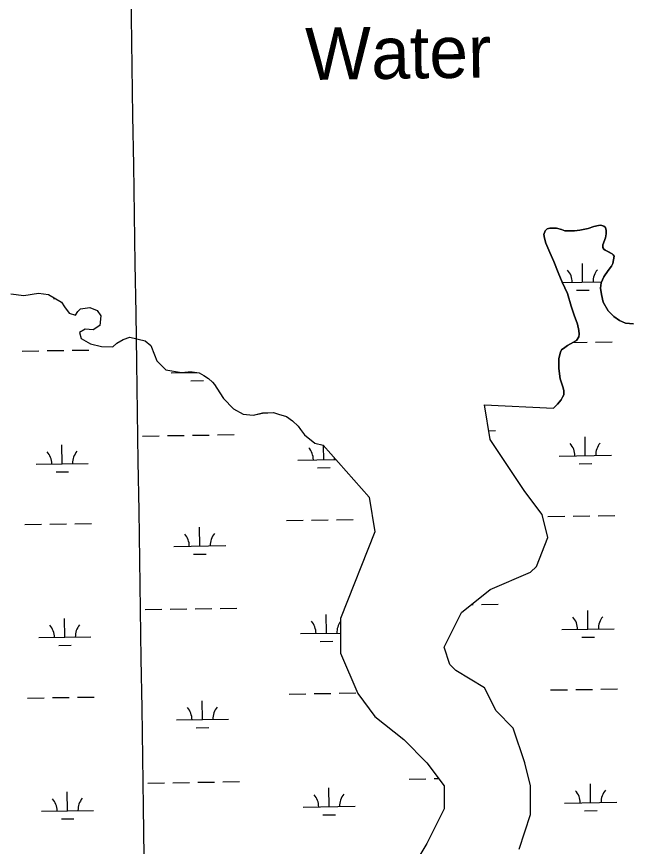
# Model space of a CAD drawing. Extents: x 3823584 to 3861785, y 301729 to 327625.
# Drawn here: x 3838149 to 3839325, y 310651 to 312242 of the extents above; entities that cross this region are included whole.
import ezdxf

# ---------------------------------------------------------------- set-up
doc = ezdxf.new("R2010")
doc.units = 0
for name, color, linetype in [('V-GRID-MAJR', 7, 'Continuous'), ('V-RIVR-IDEN', 7, 'Continuous'), ('V-TOPO-SHOR', 7, 'Continuous'), ('V-WETL-SWMP', 7, 'Continuous')]:
    doc.layers.add(name, color=color, linetype=linetype)

msp = doc.modelspace()

# ---------------------------------------------------------------- linework, layer by layer
at = {"layer": 'V-GRID-MAJR'}
msp.add_spline([(3838444.8910000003, 307319.343), (3838352.38, 313376.366), (3838259.823, 319436.473), (3838167.2660000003, 325496.576), (3838167.219, 325499.664)], degree=3, dxfattribs=at)
at = {"layer": 'V-TOPO-SHOR'}
for p, q in [((3838163.383548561, 311707.18858107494), (3838191.298548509, 311711.1795807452)), ((3838191.298548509, 311711.1795807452), (3838210.2405485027, 311709.18358070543)), ((3838138.4595485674, 311710.18158111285), (3838163.383548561, 311707.18858107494)), ((3838210.2405485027, 311709.18358070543), (3838235.1645485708, 311694.22058113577)), ((3838235.1645485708, 311694.22058113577), (3838241.1455486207, 311685.24258145)), ((3838241.1455486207, 311685.24258145), (3838250.1185486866, 311673.27258186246)), ((3838267.066548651, 311676.26458164), (3838272.051548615, 311681.2525814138)), ((3838272.051548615, 311681.2525814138), (3838289.9965485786, 311684.2455811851)), ((3838289.9965485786, 311684.2455811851), (3838303.954548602, 311678.26058133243)), ((3838250.1185486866, 311673.27258186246), (3838262.0825486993, 311669.28258194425)), ((3838262.0825486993, 311669.28258194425), (3838267.066548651, 311676.26458164)), ((3838303.954548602, 311678.26058133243), (3838310.9335486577, 311668.2845816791)), ((3838310.9335486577, 311668.2845816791), (3838308.939548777, 311649.33158243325)), ((3838308.939548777, 311649.33158243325), (3838295.9785488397, 311641.3505828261)), ((3838281.024548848, 311642.34858288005), (3838270.0575488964, 311636.36358318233)), ((3838270.0575488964, 311636.36358318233), (3838273.048548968, 311624.392583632)), ((3838295.9785488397, 311641.3505828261), (3838281.024548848, 311642.34858288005)), ((3838273.048548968, 311624.392583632), (3838290.993549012, 311614.4175839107)), ((3838333.863549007, 311608.4325838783), (3838341.838548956, 311615.4145835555)), ((3838341.838548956, 311615.4145835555), (3838353.8025489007, 311622.3975832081)), ((3838353.8025489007, 311622.3975832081), (3838366.762548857, 311627.385582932)), ((3838366.762548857, 311627.385582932), (3838395.674548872, 311620.4025830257)), ((3838395.674548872, 311620.4025830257), (3838406.641548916, 311611.42458330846)), ((3838290.993549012, 311614.4175839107), (3838311.9305490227, 311609.4295839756)), ((3838311.9305490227, 311609.4295839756), (3838333.863549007, 311608.4325838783)), ((3838406.641548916, 311611.42458330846), (3838413.6195490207, 311593.4685839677)), ((3838413.6195490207, 311593.4685839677), (3838418.6045490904, 311581.4985844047)), ((3838418.6045490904, 311581.4985844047), (3838435.552549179, 311564.5405849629)), ((3838435.552549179, 311564.5405849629), (3838465.460549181, 311559.5525849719)), ((3838465.460549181, 311559.5525849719), (3838478.421549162, 311560.55058485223)), ((3838478.421549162, 311560.55058485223), (3838486.3965491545, 311560.55058480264)), ((3838486.3965491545, 311560.55058480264), (3838499.3575491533, 311558.55458480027)), ((3838499.3575491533, 311558.55458480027), (3838508.3295491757, 311553.5675849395)), ((3838508.3295491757, 311553.5675849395), (3838517.302549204, 311547.5815851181)), ((3838517.302549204, 311547.5815851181), (3838525.2785492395, 311540.59958534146)), ((3838525.2785492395, 311540.59958534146), (3838529.266549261, 311536.6085854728)), ((3838529.266549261, 311536.6085854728), (3838539.23554935, 311520.648586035)), ((3838539.23554935, 311520.648586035), (3838546.2145494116, 311509.67558642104)), ((3838546.2145494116, 311509.67558642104), (3838565.1565495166, 311489.7245870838)), ((3838565.1565495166, 311489.7245870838), (3838584.09854956, 311479.7485873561)), ((3839058.1133026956, 311431.0057058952), (3839047.055311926, 311497.4016969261)), ((3839047.055311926, 311497.4016969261), (3839179.575, 311491.261)), ((3838584.09854956, 311479.7485873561), (3838603.041549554, 311477.75358731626)), ((3838603.041549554, 311477.75358731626), (3838620.986549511, 311481.74458704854)), ((3838620.986549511, 311481.74458704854), (3838641.9225494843, 311482.7415868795)), ((3838641.9225494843, 311482.7415868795), (3838651.8915494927, 311479.7485869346)), ((3838651.8915494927, 311479.7485869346), (3838666.846549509, 311474.76158703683)), ((3838666.846549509, 311474.76158703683), (3838678.8095495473, 311466.78058727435)), ((3838678.8095495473, 311466.78058727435), (3838689.776549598, 311456.80558759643)), ((3838689.776549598, 311456.80558759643), (3838693.7645496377, 311449.82258784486)), ((3838693.7645496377, 311449.82258784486), (3838701.7395496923, 311439.84758818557)), ((3838701.7395496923, 311439.84758818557), (3838721.6795497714, 311423.88658868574)), ((3839124.4622827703, 311331.412725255), (3839058.1133026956, 311431.0057058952)), ((3838721.6795497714, 311423.88658868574), (3838737.424791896, 311419.9449808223)), ((3838737.424791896, 311419.9449808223), (3838825.890792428, 311320.3519841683)), ((3839157.6372734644, 311287.14973429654), (3839124.4622827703, 311331.412725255)), ((3838825.890792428, 311320.3519841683), (3838836.9487928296, 311253.956986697)), ((3839168.69526686, 311242.8857407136), (3839157.6372734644, 311287.14973429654)), ((3838836.9487928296, 311253.956986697), (3838770.5997939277, 311087.9679936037)), ((3839146.579262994, 311187.55574446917), (3839168.69526686, 311242.8857407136)), ((3839135.520263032, 311176.4897444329), (3839146.579262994, 311187.55574446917)), ((3839058.113268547, 311143.292739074), (3839135.520263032, 311176.4897444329)), ((3839002.822270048, 311099.0287376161), (3839058.113268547, 311143.292739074)), ((3838969.6472662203, 311032.6337413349), (3839002.822270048, 311099.0287376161)), ((3838770.5997939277, 311087.9679936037), (3838770.5997943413, 311021.5729962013)), ((3838980.705260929, 310999.43574647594), (3838969.6472662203, 311032.6337413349)), ((3838770.5997943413, 311021.5729962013), (3838803.77479479, 310944.1109990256)), ((3838991.764258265, 310988.36974906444), (3838980.705260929, 310999.43574647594)), ((3839047.0552475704, 310955.17175945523), (3838991.764258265, 310988.36974906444)), ((3839069.1712396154, 310910.9087671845), (3839047.0552475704, 310955.17175945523)), ((3838803.77479479, 310944.1109990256), (3838836.9487950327, 310899.84800055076)), ((3838836.9487950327, 310899.84800055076), (3838892.240795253, 310855.5840019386)), ((3839102.346231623, 310877.7107749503), (3839069.1712396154, 310910.9087671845)), ((3839124.462221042, 310811.3157852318), (3839102.346231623, 310877.7107749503)), ((3838892.240795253, 310855.5840019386), (3838936.4727954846, 310811.3210033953)), ((3838936.4727954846, 310811.3210033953), (3838969.647795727, 310767.0570049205)), ((3839135.520214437, 310767.0517916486), (3839124.462221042, 310811.3157852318)), ((3838969.647795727, 310767.0570049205), (3838969.6477960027, 310722.7930066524)), ((3839135.5202078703, 310711.7227980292), (3839135.520214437, 310767.0517916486)), ((3838969.6477960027, 310722.7930066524), (3838936.4727964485, 310656.3980094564)), ((3839113.4042026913, 310645.326803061), (3839135.5202078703, 310711.7227980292)), ((3838936.4727964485, 310656.3980094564), (3838903.2987968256, 310601.0680118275))]:
    msp.add_line(p, q, dxfattribs=at)
msp.add_lwpolyline([(3839332.98, 311652.49), (3839317.823, 311654.02), (3839306.199, 311658.904), (3839294.957, 311666.941), (3839284.498, 311677.338), (3839274.805, 311694.431), (3839271.415, 311708.78500000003), (3839269.41, 311721.178), (3839270.7600000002, 311731.217), (3839276.038, 311742.844), (3839284.267, 311754.87200000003), (3839290.736, 311763.156), (3839293.474, 311768.476), (3839295.598, 311782.257), (3839294.214, 311784.811), (3839291.846, 311786.97000000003), (3839283.568, 311791.076), (3839278.643, 311793.62200000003), (3839276.273, 311795.778), (3839274.2970000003, 311798.723), (3839274.2800000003, 311804.431), (3839276.2320000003, 311809.553), (3839279.161, 311817.63), (3839280.318, 311825.308), (3839280.3000000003, 311831.803), (3839279.298, 311837.504), (3839275.946, 311840.251), (3839270.43, 311841.80700000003), (3839265.904, 311841.402), (3839256.664, 311839.208), (3839245.85, 311835.634), (3839229.921, 311832.243), (3839219.494, 311831.031), (3839210.444, 311830.80700000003), (3839201.194, 311831.174), (3839194.693, 311833.318), (3839185.043, 311836.044), (3839179.9250000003, 311836.226), (3839172.644, 311836.204), (3839167.336, 311834.811), (3839163.213, 311831.25800000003), (3839161.071, 311824.166), (3839162.273, 311816.693), (3839164.86, 311807.05700000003), (3839172.585, 311789.76300000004), (3839180.1180000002, 311772.075), (3839188.2460000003, 311751.044), (3839196.174, 311732.569), (3839206.078, 311710.756), (3839213.629, 311686.376), (3839219.1890000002, 311669.273), (3839225.341, 311651.777), (3839228.33, 311639.782), (3839228.94, 311632.7), (3839228.168, 311627.58), (3839223.269, 311620.875), (3839222.286, 311620.283), (3839206.572, 311610.987), (3839200.876, 311607.231), (3839194.593, 311602.68700000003), (3839192.637, 311598.351), (3839189.524, 311586.143), (3839189.778, 311567.25), (3839192.002, 311546.989), (3839197.556, 311532.049), (3839199.35, 311524.578), (3839199.559, 311520.249), (3839198.98, 311516.706), (3839196.829, 311511.977), (3839193.892, 311506.851), (3839187.423, 311498.76300000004), (3839179.575, 311491.261)], dxfattribs=at)
at = {"layer": 'V-WETL-SWMP'}
for p, q in [((3839235.371810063, 311732.5728008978), (3839234.8168063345, 311768.56852031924)), ((3839196.4448028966, 311731.9725961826), (3839271.628512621, 311733.1318329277)), ((3839223.6111331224, 311716.9586330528), (3839247.6082793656, 311717.3286383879)), ((3838219.9154846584, 311701.48230258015), (3838222.9896803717, 311701.5297027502)), ((3839216.4455281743, 311616.8352682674), (3839243.742614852, 311617.2561544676)), ((3839259.7407123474, 311617.50282469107), (3839291.7369073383, 311617.99616513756)), ((3838160.056487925, 311600.5464690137), (3838192.052684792, 311601.0398094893)), ((3838208.0507832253, 311601.28647972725), (3838240.0469800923, 311601.7798202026)), ((3838256.045078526, 311602.0264904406), (3838288.0412753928, 311602.51983091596)), ((3838445.582441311, 311558.5133965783), (3838494.7066282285, 311559.2708287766)), ((3838483.8158232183, 311543.6700726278), (3838507.812970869, 311544.04007798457)), ((3838534.579205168, 311439.8003434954), (3838566.575402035, 311440.29368397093)), ((3839055.311282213, 311447.83000342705), (3839068.422676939, 311448.03216438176)), ((3838390.596319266, 311437.58031135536), (3838422.592516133, 311438.0736518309)), ((3838438.5906145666, 311438.32032206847), (3838470.586811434, 311438.81366254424)), ((3838486.5849098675, 311439.06033278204), (3838518.5811067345, 311439.5536732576)), ((3839240.5005841, 311399.93735760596), (3839239.9455803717, 311435.9330770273)), ((3838236.8049763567, 311384.46101506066), (3838236.2499680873, 311420.4567358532)), ((3838738.653325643, 311392.19887541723), (3838738.2396604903, 311419.02762042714)), ((3838688.6592680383, 311391.4280309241), (3838761.754576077, 311392.5550671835)), ((3839190.506529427, 311399.16651315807), (3839290.4946387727, 311400.7082020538)), ((3838186.8109187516, 311383.69017056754), (3838286.7990339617, 311385.23185955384)), ((3838726.8926499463, 311376.5847069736), (3838750.8897975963, 311376.9547123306)), ((3839228.73990716, 311384.3231897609), (3839252.7370534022, 311384.69319509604)), ((3838225.0443006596, 311368.846846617), (3838249.04144831, 311369.216851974)), ((3839168.880901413, 311283.3873600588), (3839200.877096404, 311283.8807005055)), ((3839216.8751938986, 311284.127370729), (3839248.8713888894, 311284.62071117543)), ((3839264.8694863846, 311284.8673813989), (3839296.8656813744, 311285.3607218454)), ((3838165.1853039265, 311267.9110130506), (3838197.1815007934, 311268.40435352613)), ((3838213.179599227, 311268.65102376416), (3838245.175796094, 311269.1443642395)), ((3838261.1738945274, 311269.3910344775), (3838293.1700913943, 311269.8843749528)), ((3838667.0336532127, 311275.64887340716), (3838699.0298500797, 311276.1422138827)), ((3838715.027948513, 311276.38888412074), (3838747.02414538, 311276.88222459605)), ((3838763.0222438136, 311277.128894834), (3838795.0184406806, 311277.6222353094)), ((3838500.7053149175, 311226.6487851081), (3838500.150306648, 311262.6445059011)), ((3838450.711257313, 311225.8779406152), (3838550.6993725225, 311227.419629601)), ((3838488.9446392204, 311211.03461666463), (3838512.94178687, 311211.4046220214)), ((3838443.7194305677, 311105.6848661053), (3838475.715627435, 311106.1782065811)), ((3838491.7137258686, 311106.4248768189), (3838523.7099227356, 311106.91821729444)), ((3838539.7080211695, 311107.16488753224), (3838571.704218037, 311107.6582280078)), ((3839022.280354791, 311114.60618629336), (3839025.55715849, 311114.6567104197)), ((3839041.5552559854, 311114.9033806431), (3839073.5514509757, 311115.3967210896)), ((3838395.7251352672, 311104.9448553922), (3838427.721332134, 311105.43819586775)), ((3838743.7821416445, 311059.5634194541), (3838743.227133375, 311095.55914024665)), ((3839245.6293581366, 311067.3019143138), (3839245.0743544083, 311103.2976337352)), ((3838241.9337923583, 311051.8255590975), (3838241.3787840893, 311087.8212798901)), ((3838693.78808404, 311058.792574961), (3838770.599794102, 311059.9769133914)), ((3839195.635303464, 311066.531069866), (3839295.6234128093, 311068.07275876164)), ((3838191.9397347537, 311051.0547146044), (3838291.9278499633, 311052.5964035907)), ((3838732.021465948, 311043.94925101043), (3838756.018613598, 311044.31925636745)), ((3839233.868681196, 311051.6877464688), (3839257.8658274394, 311052.0577518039)), ((3838230.173116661, 311036.21139065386), (3838254.1702643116, 311036.5813960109)), ((3839174.00967545, 310950.75191676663), (3839206.0058704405, 310951.24525721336)), ((3839222.0039679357, 310951.49192743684), (3839254.0001629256, 310951.9852678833)), ((3839269.998260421, 310952.23193810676), (3839301.994455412, 310952.72527855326)), ((3838170.3141199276, 310935.27555708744), (3838202.310316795, 310935.768897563)), ((3838218.308415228, 310936.015567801), (3838250.3046120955, 310936.50890827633)), ((3838266.302710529, 310936.75557851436), (3838298.298907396, 310937.2489189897)), ((3838672.162469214, 310943.013417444), (3838704.1586660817, 310943.50675791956)), ((3838720.1567645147, 310943.7534281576), (3838752.152961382, 310944.2467686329)), ((3838768.1510598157, 310944.49343887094), (3838800.1472566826, 310944.98677934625)), ((3838505.8341309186, 310894.013329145), (3838505.279122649, 310930.00904993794)), ((3838455.8400733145, 310893.24248465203), (3838555.828188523, 310894.78417363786)), ((3838494.073455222, 310878.39916070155), (3838518.070602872, 310878.76916605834)), ((3838400.8539512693, 310772.30939942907), (3838432.8501481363, 310772.80273990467)), ((3838448.8482465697, 310773.0494101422), (3838480.8444434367, 310773.542750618)), ((3838496.84254187, 310773.78942085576), (3838528.838738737, 310774.2827613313)), ((3838544.8368371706, 310774.5294315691), (3838576.8330340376, 310775.02277204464)), ((3838902.7023005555, 310780.0472597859), (3838934.6984974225, 310780.5406002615)), ((3838950.696595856, 310780.787270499), (3838959.258291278, 310780.9192809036)), ((3838748.9109576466, 310726.92796349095), (3838748.3559493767, 310762.9236842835)), ((3839250.7581321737, 310734.66647102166), (3839250.2031284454, 310770.662190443)), ((3838247.06260836, 310719.1901031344), (3838246.50760009, 310755.18582392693)), ((3838698.9169000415, 310726.1571189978), (3838798.905015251, 310727.6988079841)), ((3839200.764077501, 310733.8956265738), (3839300.7521868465, 310735.4373154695)), ((3838197.0685507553, 310718.41925864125), (3838297.0566659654, 310719.96094762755)), ((3838737.150281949, 310711.3137950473), (3838761.147429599, 310711.6838004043)), ((3839238.9974552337, 310719.05230317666), (3839262.994601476, 310719.42230851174)), ((3838235.301932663, 310703.5759346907), (3838259.2990803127, 310703.94594004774))]:
    msp.add_line(p, q, dxfattribs=at)
for points in [[(3839113.404, 310645.327), (3839135.52, 310711.723), (3839135.52, 310767.052), (3839124.4620000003, 310811.316), (3839102.346, 310877.711), (3839069.171, 310910.909), (3839047.055, 310955.172), (3838991.764, 310988.37), (3838980.705, 310999.436), (3838969.647, 311032.634), (3839002.822, 311099.029), (3839058.113, 311143.293), (3839135.52, 311176.49), (3839146.579, 311187.556), (3839168.6950000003, 311242.886), (3839157.637, 311287.15), (3839124.4620000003, 311331.413), (3839058.113, 311431.006), (3839047.055, 311497.402), (3839179.574, 311491.262), (3839187.423, 311498.76300000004), (3839193.893, 311506.851), (3839196.83, 311511.976), (3839198.98, 311516.705), (3839199.56, 311520.249), (3839199.35, 311524.578), (3839197.557, 311532.05), (3839192.003, 311546.989), (3839189.778, 311567.251), (3839189.525, 311586.142), (3839192.637, 311598.352), (3839194.592, 311602.68700000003), (3839200.876, 311607.232), (3839206.571, 311610.987), (3839223.268, 311620.876), (3839228.168, 311627.581), (3839228.94, 311632.7), (3839228.329, 311639.783), (3839225.341, 311651.777), (3839219.1890000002, 311669.273), (3839213.628, 311686.377), (3839206.078, 311710.755), (3839196.174, 311732.569), (3839188.247, 311751.043), (3839180.117, 311772.075), (3839172.586, 311789.76300000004), (3839164.86, 311807.05700000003), (3839162.273, 311816.692), (3839161.071, 311824.166), (3839163.214, 311831.257), (3839167.336, 311834.811), (3839172.645, 311836.204), (3839179.926, 311836.226), (3839185.043, 311836.044), (3839194.693, 311833.318), (3839201.194, 311831.173), (3839210.444, 311830.80700000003), (3839219.495, 311831.031), (3839229.921, 311832.242), (3839245.85, 311835.635), (3839256.663, 311839.20900000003), (3839265.9050000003, 311841.401), (3839270.43, 311841.808), (3839275.9450000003, 311840.25), (3839279.298, 311837.505), (3839280.299, 311831.802), (3839280.318, 311825.308), (3839279.161, 311817.63), (3839274.2800000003, 311804.431), (3839274.2970000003, 311798.724), (3839276.274, 311795.778), (3839278.642, 311793.621)], [(3839278.642, 311793.621), (3839291.846, 311786.969), (3839294.214, 311784.81200000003), (3839295.599, 311782.25800000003), (3839293.475, 311768.476), (3839290.736, 311763.155), (3839284.267, 311754.871), (3839276.038, 311742.843), (3839270.759, 311731.217), (3839269.411, 311721.177), (3839271.416, 311708.78500000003), (3839274.804, 311694.43), (3839284.497, 311677.339), (3839294.958, 311666.94), (3839306.198, 311658.905), (3839317.823, 311654.02), (3839332.98, 311652.491)], [(3838138.4620000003, 311710.197), (3838163.386, 311707.204), (3838191.301, 311711.195), (3838210.2430000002, 311709.199), (3838235.167, 311694.23600000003), (3838241.148, 311685.25800000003), (3838250.1210000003, 311673.288), (3838262.085, 311669.298), (3838267.069, 311676.28), (3838272.054, 311681.268), (3838289.9990000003, 311684.261), (3838303.957, 311678.276), (3838310.936, 311668.3), (3838308.9420000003, 311649.347), (3838295.981, 311641.366), (3838281.0270000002, 311642.364), (3838270.06, 311636.379), (3838273.051, 311624.408), (3838290.9960000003, 311614.433), (3838311.933, 311609.445), (3838333.866, 311608.44800000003), (3838341.841, 311615.43), (3838353.805, 311622.413), (3838366.765, 311627.401), (3838395.677, 311620.418), (3838406.644, 311611.44), (3838413.622, 311593.484), (3838418.6070000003, 311581.514), (3838435.555, 311564.556), (3838465.463, 311559.568), (3838478.424, 311560.566), (3838486.399, 311560.566), (3838499.36, 311558.57), (3838508.332, 311553.583), (3838517.305, 311547.597), (3838525.281, 311540.615), (3838529.269, 311536.624), (3838539.238, 311520.664), (3838546.217, 311509.691), (3838565.159, 311489.74), (3838584.1010000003, 311479.764), (3838603.044, 311477.76900000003), (3838620.989, 311481.76), (3838641.9250000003, 311482.757), (3838651.894, 311479.764), (3838666.849, 311474.777), (3838678.812, 311466.79600000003), (3838689.779, 311456.821), (3838693.767, 311449.838), (3838701.742, 311439.863), (3838721.682, 311423.902), (3838737.424, 311419.94), (3838825.89, 311320.347), (3838836.948, 311253.952), (3838770.599, 311087.963), (3838770.599, 311021.568)], [(3838770.599, 311021.568), (3838803.774, 310944.106), (3838836.948, 310899.843), (3838892.24, 310855.579), (3838936.472, 310811.316), (3838969.647, 310767.052), (3838969.647, 310722.788), (3838936.472, 310656.393), (3838903.298, 310601.063)]]:
    msp.add_lwpolyline(points, dxfattribs=at)
for centre, radius, start, end in [((3839180.128122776, 311732.1958734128), 35.24628790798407, 0.11153765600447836, 41.65519598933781), ((3839290.600857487, 311733.8992218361), 35.24628790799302, 140.11153465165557, 181.6551929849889), ((3838440.332808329, 311558.90731355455), 35.24628790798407, 0.1115376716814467, 2.3125187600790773), ((3838292.0340269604, 311385.7874360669), 35.246287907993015, 140.11153463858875, 181.65519297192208), ((3838683.4096350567, 311391.8219479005), 35.24628790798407, 0.11153767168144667, 41.65519600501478), ((3839185.2568968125, 311399.56043012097), 35.24628790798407, 0.11153765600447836, 41.65519598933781), ((3839295.7296315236, 311401.2637785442), 35.24628790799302, 140.11153465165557, 181.6551929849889), ((3838181.5612857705, 311384.08408754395), 35.24628790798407, 0.11153767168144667, 41.65519600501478), ((3838793.882376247, 311393.52529642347), 35.246287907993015, 176.02239346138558, 181.65519297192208), ((3838445.4616243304, 311226.2718575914), 35.24628790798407, 0.11153767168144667, 41.65519600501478), ((3838555.934365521, 311227.9752061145), 35.246287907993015, 140.11153463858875, 181.65519297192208), ((3839190.3856708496, 311066.9249868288), 35.24628790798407, 0.11153765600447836, 41.65519598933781), ((3839300.8584055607, 311068.62833525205), 35.24628790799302, 140.11153465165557, 181.6551929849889), ((3838186.690101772, 311051.44863158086), 35.24628790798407, 0.11153767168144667, 41.65519600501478), ((3838297.1628429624, 311053.15198010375), 35.246287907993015, 140.11153463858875, 181.65519297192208), ((3838688.5384510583, 311059.1864919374), 35.24628790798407, 0.11153767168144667, 41.65519600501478), ((3838799.011192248, 311060.8898404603), 35.246287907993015, 143.71487936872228, 181.65519297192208), ((3838450.5904403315, 310893.63640162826), 35.24628790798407, 0.11153767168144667, 41.65519600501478), ((3838561.0631815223, 310895.3397501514), 35.246287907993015, 140.11153463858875, 181.65519297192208), ((3839195.5144448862, 310734.28954353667), 35.24628790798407, 0.11153765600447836, 41.65519598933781), ((3839305.9871795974, 310735.9928919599), 35.24628790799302, 140.11153465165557, 181.6551929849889), ((3838191.818917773, 310718.8131756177), 35.24628790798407, 0.11153767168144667, 41.65519600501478), ((3838302.2916589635, 310720.5165241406), 35.246287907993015, 140.11153463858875, 181.65519297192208), ((3838693.6672670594, 310726.5510359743), 35.24628790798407, 0.11153767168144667, 41.65519600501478), ((3838804.1400082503, 310728.2543844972), 35.246287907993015, 140.11153463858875, 181.65519297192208)]:
    msp.add_arc(centre, radius, start, end, dxfattribs=at)

# ---------------------------------------------------------------- texts
at = {"layer": 'V-RIVR-IDEN'}
msp.add_text('Water', height=99.99980199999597, rotation=0.8425138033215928, dxfattribs=at).set_placement((3838704.024552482, 312120.0087346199))

doc.saveas('drawing.dxf')
